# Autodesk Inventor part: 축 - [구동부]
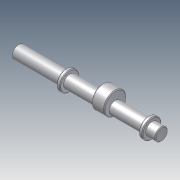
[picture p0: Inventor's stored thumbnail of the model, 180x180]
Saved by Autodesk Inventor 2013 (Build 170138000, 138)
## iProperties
Company: 한국ATC센터
Created: 2014-08
Part Number: 축 - [구동부]
Document SubType Name: Modeling
Designer: KYOUNG IL JANG
Density: 1 g/cm^3
Material: 일반
Mass: 54.4474 g
Surface Area: 136.7 cm^2
Volume: 54.4474 cm^3
Author: KYOUNG IL JANG
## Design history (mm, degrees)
sketch "스케치1"
  geometry: L1 (-96.5, 0)-(96.5, 0); L2 (-96.5, 0)-(-96.5, 8.5); L3 (-96.5, 8.5)-(-32.5, 8.5); L4 (-32.5, 8.5)-(-32.5, 13); L5 (-32.5, 13)-(-27.5, 13); L6 (-27.5, 13)-(-27.5, 8.5); L7 (-27.5, 8.5)-(78.5, 8.5); L8 (78.5, 8.5)-(78.5, 13); L9 (78.5, 13)-(83.5, 13); L10 (83.5, 13)-(83.5, 8.5); L11 (83.5, 8.5)-(96.5, 8.5); L12 (96.5, 8.5)-(96.5, 0); 2 further points
  constraints: 24 end point, 5 parallel, 1 coincident, 1 horizontal, 1 midpoint, 1 perpendicular
  dimensions: "d0" = 193 distance of L1.start L1.end (derived); "d2" = 17 diameter of L3 L1; "d3" = 26 diameter of L5 L1; "d4" = 17 diameter of L7 L1; "d5" = 26 diameter of L9 L1; "d6" = 17 diameter of L11 L1; "d7" = 5 distance of L8.end L9.end; "d8" = 5 distance of L4.end L5.end; "d10" = 64 distance of L2.end L3.end; "d11" = 13 distance of L10.end L11.end; "d35" = 106 distance between parallel lines of L8 L6
revolve "회전1" sketch "스케치1" stored, may be unused: angle "d12" = 90 deg
node "작업 평면1"
node "작업 평면2"
node "작업 평면4"
sketch "스케치6"
  geometry: C1 r 15 at (-5, -6); 1 further point
  constraints: 1 centre point, 1 horizontal alignment
  dimensions: "d31" = 30 diameter of C1; "d32" = 5 distance of C1.centre point (0, -6)
extrude "돌출4" join sketch "스케치6" stored distance "d33" = 17; taper "d34" = 0 deg
node "작업 평면3"
sketch "스케치5"
  geometry: L1 (32, 8.5)-(32, -8.5) reference; L2 (32, -2.5)-(14.5, -2.5); L3 (14.5, 2.5)-(32, 2.5); A1 r 2.5 centre (14.5, 0) between (14.5, 2.5) and (14.5, -2.5); 2 further points
  constraints: 4 end point, 2 point on circle, 2 point on line, 2 tangent, 1 centre point, 1 midpoint, 1 parallel, 1 perpendicular
  dimensions: "d23" = 5 distance between parallel lines of L3 L2; "d36" = 20 dimension on A1 L1
extrude "돌출3" cut sketch "스케치5" distance "d25" = 3; taper "d26" = 0 deg
chamfer "모따기1" distance "d27" = 1; stored, may be unused: second distance "d28" = 2, angle "d29" = 45 deg
node "솔리드1"
other parameters: "d13" = 9.5, "d18" = 9.5
